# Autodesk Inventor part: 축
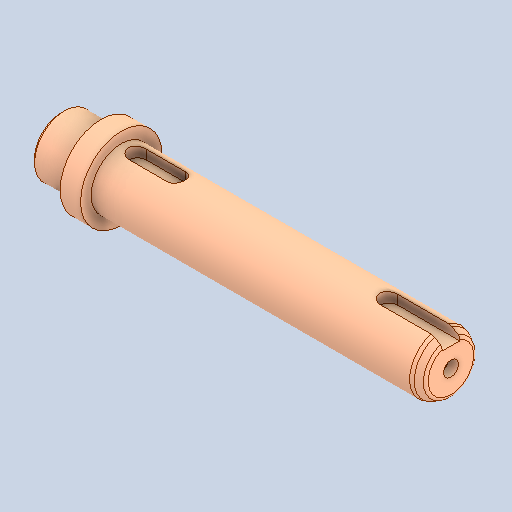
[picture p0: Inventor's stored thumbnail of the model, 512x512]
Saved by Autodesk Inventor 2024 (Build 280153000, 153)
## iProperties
Created: 2026-01
Part Number: 축
Material: 강철, 탄소
Document SubType Name: Modeling
Designer: 2-10
Density: 7.85 g/cm^3
Appearance: 기본값
Sending System: Autodesk Inventor 2026
Preprocessor: ST-DEVELOPER v20.1
Author: jhkim
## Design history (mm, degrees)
node "축1"
node "솔리드2"
node "솔리드1"
